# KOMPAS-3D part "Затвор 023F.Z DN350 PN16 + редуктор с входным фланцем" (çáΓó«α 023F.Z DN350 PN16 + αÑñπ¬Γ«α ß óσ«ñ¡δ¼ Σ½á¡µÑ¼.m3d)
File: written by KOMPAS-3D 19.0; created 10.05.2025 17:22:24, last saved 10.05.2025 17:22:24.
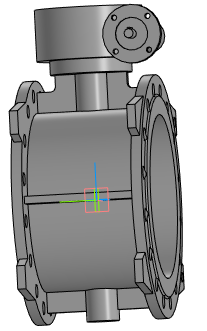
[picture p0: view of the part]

Document properties: Полное имя файла: Затвор 023F.Z DN350 PN16 + редуктор с входным фланцем.a3d

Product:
- Part/product: Затвор 023F.Z DN350 PN16 + редуктор с входным фланцем
    Масса: 168.305

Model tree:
1. Операция без истории:1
